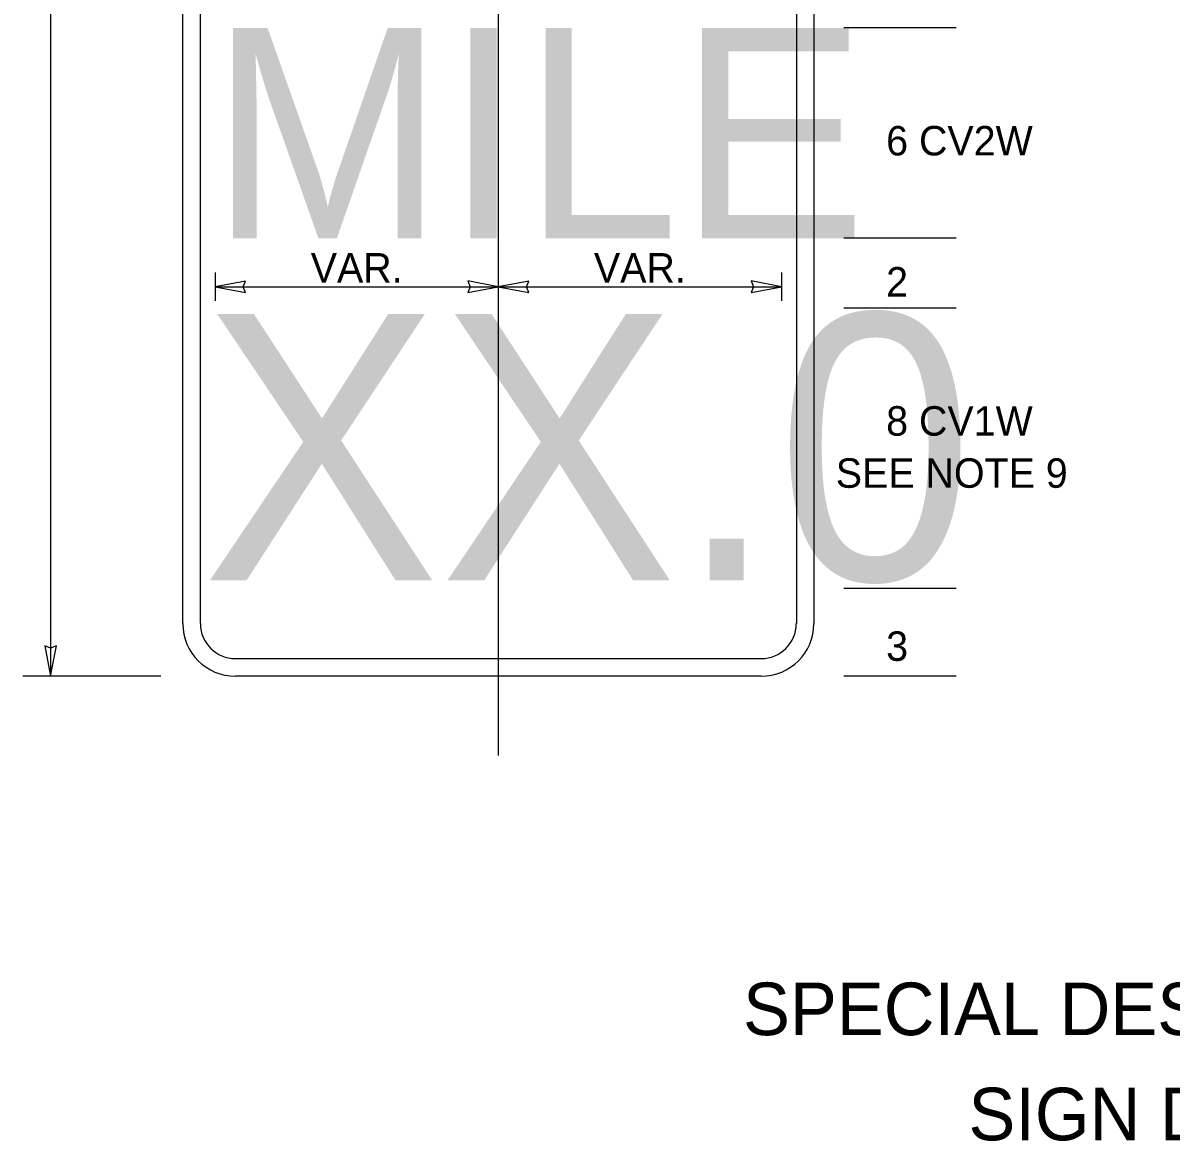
# Model space of a CAD drawing. Extents: x 56108 to 56734, y 11696 to 12110.
# Drawn here: x 56514.4 to 56623.6, y 11709 to 11815.3 of the extents above; entities that cross this region are included whole.
import ezdxf

# ---------------------------------------------------------------- set-up
doc = ezdxf.new("R2010")
doc.units = 0
for name, color, linetype in [('CL_dp', 7, 'Continuous'), ('GSDims', 7, 'Continuous'), ('SignPanel', 7, 'Continuous'), ('TextMisc', 7, 'Continuous')]:
    doc.layers.add(name, color=color, linetype=linetype)

msp = doc.modelspace()

# ---------------------------------------------------------------- linework, layer by layer
at = {"layer": 'CL_dp'}
msp.add_line((56559.63, 11917.97), (56559.63, 11745.62), dxfattribs=at)
at = {"layer": 'GSDims'}
for p, q in [((56517.04, 11913.16), (56517.04, 11753.16)), ((56603.18, 11814.82), (56592.5, 11814.82)), ((56603.18, 11794.82), (56592.5, 11794.82)), ((56532.7, 11791.55), (56532.7, 11788.86)), ((56586.57, 11791.55), (56586.57, 11788.86)), ((56535.6, 11790.74), (56532.7, 11790.2)), ((56532.7, 11790.2), (56559.63, 11790.2)), ((56532.7, 11790.2), (56535.6, 11789.64)), ((56535.38, 11790.2), (56535.6, 11790.74)), ((56535.6, 11789.64), (56535.38, 11790.2)), ((56559.63, 11790.2), (56556.73, 11790.76)), ((56556.73, 11790.76), (56556.95, 11790.2)), ((56556.95, 11790.2), (56556.73, 11789.66)), ((56556.73, 11789.66), (56559.63, 11790.2)), ((56562.53, 11790.74), (56559.63, 11790.2)), ((56559.63, 11790.2), (56586.57, 11790.2)), ((56559.63, 11790.2), (56562.53, 11789.64)), ((56562.31, 11790.2), (56562.53, 11790.74)), ((56562.53, 11789.64), (56562.31, 11790.2)), ((56586.57, 11790.2), (56583.67, 11790.76)), ((56583.67, 11790.76), (56583.89, 11790.2)), ((56583.89, 11790.2), (56583.67, 11789.66)), ((56583.67, 11789.66), (56586.57, 11790.2)), ((56603.18, 11788.16), (56592.5, 11788.16)), ((56603.18, 11761.49), (56592.5, 11761.49)), ((56517.04, 11755.84), (56516.5, 11756.06)), ((56516.5, 11756.06), (56517.04, 11753.16)), ((56517.04, 11753.16), (56517.6, 11756.06)), ((56517.6, 11756.06), (56517.04, 11755.84)), ((56527.55, 11753.16), (56514.42, 11753.16)), ((56603.18, 11753.16), (56592.5, 11753.16))]:
    msp.add_line(p, q, dxfattribs=at)
at = {"layer": 'SignPanel'}
for points in [[(56529.63, 11758.16), (56529.63, 11908.16)], [(56531.3, 11758.16), (56531.3, 11908.16)], [(56587.97, 11908.16), (56587.97, 11758.16)], [(56589.63, 11908.16), (56589.63, 11758.16)], [(56584.63, 11754.82), (56534.63, 11754.82)], [(56584.63, 11753.16), (56534.63, 11753.16)]]:
    msp.add_lwpolyline(points, dxfattribs=at)
for centre, radius, start, end in [((56534.63, 11758.16), 5, 180, 270), ((56534.63, 11758.16), 3.33, 180, 270), ((56584.63, 11758.16), 5, 270, 360), ((56584.63, 11758.16), 3.33, 270, 360)]:
    msp.add_arc(centre, radius, start, end, dxfattribs=at)

# ---------------------------------------------------------------- texts
at = {"layer": 'GSDims'}
for s, p in [('6 CV2W', (56596.51, 11802.69)), ('VAR.', (56541.79, 11790.6)), ('VAR.', (56568.72, 11790.6)), ('2', (56596.51, 11789.27)), ('8 CV1W', (56596.51, 11776.04)), ('SEE NOTE 9', (56591.72, 11771.08)), ('3', (56596.51, 11754.62))]:
    msp.add_text(s, height=2.8, dxfattribs=at).set_placement(p)
at = {"layer": 'SignPanel'}
for s, height, p in [('MILE', 20, (56532.22, 11794.8)), ('XX.0', 25.333, (56531.45, 11762.29))]:
    msp.add_text(s, height=height, dxfattribs=at).set_placement(p)
at = {"layer": 'TextMisc'}
for s, p in [('SPECIAL DESIGN MILEPOST ', (56582.9, 11719.02)), ('      SIGN DETAILS      ', (56593.19, 11709.02))]:
    msp.add_text(s, height=5, rotation=360, dxfattribs=at).set_placement(p)

doc.saveas('drawing.dxf')
